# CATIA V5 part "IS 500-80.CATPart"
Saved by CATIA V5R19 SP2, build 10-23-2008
Part number: IS 500-80
Bounding box of the stored display mesh (mm): x -22.494 to 22.494, y -22.494 to 22.494, z 0 to 245
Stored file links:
  C:\Users\Bora\Desktop\3D Katı model\IS serisi\IS 500\IS 500-80.CATPart
  C:\Program Files\Dassault Systemes\B19\intel_a\reffiles\standard\MetricThickPitch.txt
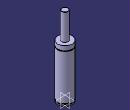
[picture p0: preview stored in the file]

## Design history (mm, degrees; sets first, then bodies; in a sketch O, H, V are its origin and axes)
Body1 (main body)
  Sketch1 on yz-plane, origin (0, 0, 0), H (0, 1, 0), V (0, 0, 1)
    point P3 (10, 244)
    point P5 (10, 244)
    point P7 (22.5, 149.5)
    point P8 (22.5, 147.5)
    point P12 (22.5, 147.5)
    point P13 (22.5, 149.5)
    line L1 (22.5, 0) -> (22.5, 4)
    line L2 (10, 244) -> (10, 163)
    arc A1 centre (9, 244) radius 1 from (10, 244) to (9, 245) ccw
    arc A2 centre (22.5, 148.5) radius 1 from (22.5, 149.5) to (22.5, 147.5) ccw
    line L3 (20, 7.5) -> (20, 4)
    line L4 (22.5, 7.5) -> (22.5, 147.5)
    line L5 (22.5, 149.5) -> (22.5, 163)
    line L6 (9, 245) -> (0, 245)
    point P15 (0, 245)
    line L7 (10, 163) -> (22.5, 163)
    line L8 (0, 0) -> (22.5, 0)
    line L9 (20, 4) -> (22.5, 4)
    line L10 (20, 7.5) -> (22.5, 7.5)
    coincidence: P15 V, P3 P5, P7 P13, P8 P12
    tangency: L6 A1
    horizontal: L7 H, L8 H, L9 H, L10 H
  Shaft1: profile Sketch1, axis Sketch1.V, angle 360
  Sketch2 on face of Shaft1 from Sketch1.L8, origin (0, 0, 0), H (1, 0, 0), V (0, -1, 0)
    point P1 (10, 0)
    distance P1 V = 10
  Hole1: placed by Sketch2, at (10, 0, 0) direction (0, 0, 1), diameter 6.647, depth 13, threaded "M8", thread diameter 8, thread depth 13, pitch 1.25
  Sketch3 on face of Shaft1 from Sketch1.L8, origin (0, 0, 0), H (1, 0, 0), V (0, -1, 0)
    point P1 (-10, 0)
    distance P1 V = 10
  Hole2: placed by Sketch3, at (-10, 0, 0) direction (0, 0, 1), diameter 6.647, depth 13, threaded "M8", thread diameter 8, thread depth 13, pitch 1.25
